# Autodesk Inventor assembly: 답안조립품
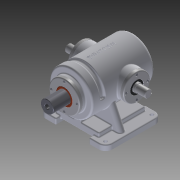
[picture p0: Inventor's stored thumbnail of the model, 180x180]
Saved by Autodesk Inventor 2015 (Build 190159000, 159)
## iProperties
Created: 2015-10
Part Number: 답안조립품
Document SubType Name: Assembly
Designer: youjin19
Author: youjin19
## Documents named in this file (13)
- C:\Users\youjin19\Desktop\351019V1007\답안조립품.iam
- C:\Users\youjin19\Desktop\351019V1007\본체.ipt
- C:\Users\youjin19\Desktop\351019V1007\슬라이드 커버.ipt
- C:\Users\youjin19\Desktop\351019V1007\M4x0.7.ipt
- C:\Users\youjin19\Desktop\351019V1007\부시.ipt
- C:\Users\youjin19\Desktop\351019V1007\베어링 6205.ipt
- 베어링 6205.ipt
- C:\Users\youjin19\Desktop\351019V1007\축 커버.ipt
- C:\Users\youjin19\Desktop\351019V1007\오일실.ipt
- 오일실.ipt
- C:\Users\youjin19\Desktop\351019V1007\편심축.ipt
- C:\Users\youjin19\Desktop\351019V1007\가변 스프링.ipt
- C:\Users\youjin19\Desktop\351019V1007\슬라이드.ipt
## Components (13 placed, 2 different names)
1. 가변 스프링:1 — Mate:22, Mate:23, Mate:24, Mate:25
2. M4x0.7:1 — Insert:1
3. M4x0.7:2
4. M4x0.7:3
5. M4x0.7:4
6. M4x0.7:5 — Insert:2
7. M4x0.7:6
8. M4x0.7:7
9. M4x0.7:8
10. M4x0.7:9 — Insert:3
11. M4x0.7:10
12. M4x0.7:11
13. M4x0.7:12
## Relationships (7: Mate 4, Insert 3)
- Insert:1: M4x0.7:1
- Insert:2: M4x0.7:5
- Insert:3: M4x0.7:9
- Mate:22: 가변 스프링:1
- Mate:23: 가변 스프링:1
- Mate:24: 가변 스프링:1
- Mate:25: 가변 스프링:1
